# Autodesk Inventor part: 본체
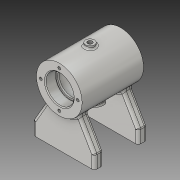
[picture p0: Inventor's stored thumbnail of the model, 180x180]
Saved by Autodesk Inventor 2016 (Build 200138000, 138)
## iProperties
Created: 2018-05
Part Number: 본체
Material: 알루미늄 6061
Document SubType Name: Modeling
Designer: Administrator
Density: 2.7 g/cm^3
Appearance: 알루미늄 - 평지
Mass: 319.096 g
Surface Area: 369.089 cm^2
Volume: 118.184 cm^3
Author: Administrator
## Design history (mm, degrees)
node "작업 평면1"
sketch "스케치1"
  geometry: L1 (6.132, 65)-(-6.132, 65); L2 (-35, 0)-(35, 0); L3 (6.132, 65)-(35, 15); L4 (35, 15)-(35, 0); L5 (-6.132, 65)-(-35, 15); L6 (-35, 15)-(-35, 0); 2 further points
  constraints: 12 end point, 1 coincident, 1 horizontal, 1 midpoint, 1 parallel, 1 perpendicular, 1 vertical
  dimensions: "d1" = 70 distance of L2.start L2.end; "d4" = 30 deg angle of L4 L3; "d5" = 30 deg angle of L6 L5; "d6" = 65 distance between parallel lines of L2 L1; "d7" = 15 distance of L5.end L2.start; "d8" = 15 distance of L3.end L2.end
extrude "돌출1" new body sketch "스케치1" distance "d9" = 10; taper "d10" = 0 deg
sketch "스케치2"
  geometry: L1 (35, 0)-(-35, 0) reference; C1 r 26 at (0, 65); 2 further points
  constraints: 1 centre point, 1 midpoint, 1 vertical alignment
  dimensions: "d11" = 65 distance from line of L1 C1.centre; "d12" = 52 diameter of C1
extrude "돌출2" join sketch "스케치2" distance "d13" = 35; taper "d14" = 0 deg
sketch "스케치3"
  geometry: L1 (35, 39)-(35, 91) reference; L2 (35, 65)-(0, 65); L3 (0, 91)-(0, 39) reference; L4 (21, 86)-(0, 86); L5 (21, 86)-(21, 79); L6 (21, 79)-(23, 79); L7 (23, 79)-(23, 81); L8 (23, 81)-(35, 81); L9 (35, 81)-(35, 65); L10 (0, 86)-(0, 65); 1 further point
  constraints: 16 end point, 4 perpendicular, 2 point on line, 1 collinear, 1 horizontal, 1 midpoint, 1 vertical
  dimensions: "d15" = 42 diameter of L4 L2; "d16" = 28 diameter of L6 L2; "d17" = 32 diameter of L8 L2; "d18" = 21 distance of L4.start L4.end; "d19" = 12 distance of L7.end L8.end
revolve "회전1" sketch "스케치3" stored, may be unused: angle "d20" = 90 deg
sketch "스케치4"
  geometry: C1 r 16 at (0, 0) reference; 2 further points
  constraints: 1 vertical alignment
  dimensions: "d21" = 21 distance of C1.centre point (0, -21)
hole "구멍1" sketch "스케치4" at (0, -21) diameter "d22" = 3.242; stored, may be unused: countersink angle "d26" = 90 deg, drill point angle "d28" = 118 deg; dims "d23" = 8, "d24" = 4, "d25" = 2, "d27" = 10
node "작업 평면2"
sketch "스케치5"
  geometry: C1 r 5 at (0, 0); 1 further point
  constraints: 1 centre point, 1 coincident
  dimensions: "d33" = 10 diameter of C1
extrude "돌출3" join sketch "스케치5" stored distance "d34" = 35; taper "d35" = 0 deg
hole "구멍2" diameter "d38" = 5.188; stored, may be unused: countersink angle "d42" = 90 deg, drill point angle "d44" = 118 deg; dims "d36" = 10, "d37" = 10, "d39" = 12, "d40" = 4, "d41" = 2, "d43" = 16
sketch "스케치6"
  geometry: L1 (0, 65)-(-9.919, 37.749); L2 (-9.919, 37.749)-(-15.557, 39.801); L3 (-15.557, 39.801)-(-13.163, 46.379); L4 (-13.163, 46.379)-(-7.524, 44.327); L5 (0, 65)-(0, 33.027); C1 r 14 at (0, 65) reference; 1 further point
  constraints: 10 end point, 2 perpendicular, 1 parallel, 1 point on line, 1 vertical
  dimensions: "d45" = 29 distance of L1.start L1.end; "d46" = 6 distance of L1.end L2.end; "d47" = 20 deg angle of L5 L1; "d48" = 7 distance of L2.end L3.end
revolve "회전2" sketch "스케치6" stored, may be unused: angle "d49" = 90 deg
hole "구멍3" diameter "d52" = 5.188; stored, may be unused: countersink angle "d56" = 90 deg, drill point angle "d58" = 118 deg; dims "d53" = 12, "d54" = 4, "d55" = 2, "d57" = 16, "d81" = 10, "d82" = 10
fillet "모깎기1" dims "d59" = 2
fillet "모깎기2" dims "d60" = 0.3
fillet "모깎기3" dims "d61" = 3
fillet "모깎기4" dims "d62" = 3
fillet "모깎기5" dims "d63" = 3
fillet "모깎기6" dims "d64" = 3
chamfer "모따기1" distance "d65" = 1; stored, may be unused: second distance "d66" = 2, angle "d67" = 45 deg
sketch "스케치8"
  geometry: L1 (64, 0)-(0, 0) reference; 2 further points
  dimensions: "d72" = 20 horizontal distance of point (32, -20) point (12, 5); "d73" = 5 distance from line of L1 point (12, 5)
hole "구멍4" sketch "스케치8" at (12, 5) diameter "d74" = 4.134; stored, may be unused: countersink angle "d78" = 90 deg, drill point angle "d80" = 118 deg; dims "d75" = 8, "d76" = 4, "d77" = 2, "d79" = 10
node "작업 평면4"
sketch "스케치9"
  geometry: L1 (35, 26)-(-35, 26) reference; L2 (-35, 26)-(-35, -26) reference; 2 further points
  constraints: 1 other
  dimensions: "d83" = 26 distance from line of L1 point (1, 0); "d84" = 36 distance from line of L2 point (1, 0)
feature "엠보싱2" sketch "스케치9" dims "d1" = 70, "d4" = 30 deg, "d5" = 30 deg, "d6" = 65, "d7" = 15, "d8" = 15, "d15" = 42, "d16" = 28, "d17" = 32, "d18" = 21, "d19" = 12, "d85" = 0.5, "d86" = 0
node "솔리드1"
mirror "대칭1"
pattern_circular "원형 패턴1" dims angle "d30" = 360 deg
mirror "대칭2"
mirror "대칭3"
mirror "대칭4"
other parameters: "d32" = 94
